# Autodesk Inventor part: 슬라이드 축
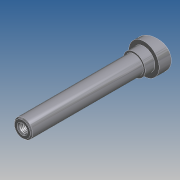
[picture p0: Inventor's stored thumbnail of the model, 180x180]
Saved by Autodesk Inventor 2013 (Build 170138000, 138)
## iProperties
Company: 한국ATC센터
Created: 2012-05
Part Number: 슬라이드 축
Document SubType Name: 모델링
Designer: KYOUNG IL JANG
Mass: 169.556 g
Surface Area: 67.5858 cm^2
Volume: 21.572 cm^3
Density: 7.86 g/cm^3
Material: 강, 연강
변환 표준: STEP AP214IS
파일 이름: C:\Users\SeoGD\Desktop\?쒗뿕\異?stp
전처리기: Build: 253, Release: 2010 SP1 - Date: Wed 07/29/2009
전송 단위: 밀리미터
불확실성: 0.01
Author: KYOUNG IL JANG
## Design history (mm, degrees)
sketch "스케치1"
  geometry: L1 (0, 100)-(7.5, 100); L2 (7.5, 100)-(7.5, 0); L3 (7.5, 0)-(12.5, 0); L4 (12.5, 0)-(12.5, -17); L5 (12.5, -17)-(0, -17); L6 (0, -17)-(0, 100); 1 further point
  constraints: 12 end point, 2 parallel, 2 point on line, 1 perpendicular, 1 vertical
  dimensions: "d0" = 100 distance from line of L1 point (0, 0); "d1" = 15 diameter of L2 L6; "d2" = 25 diameter of L4 L6; "d3" = 17 distance of L3.end L4.end
revolve "회전1" sketch "스케치1" stored, may be unused: angle "d4" = 90 deg
sketch "스케치2"
  geometry: L1 (12.5, 0)-(12.5, -17) reference; L2 (-12.5, -17)-(12.5, -17) reference; L3 (-12.5, 0)-(-12.5, -17) reference; L4 (12.5, -5)-(-12.5, -11.699); L5 (-12.5, 0)-(12.5, 0) reference; 1 further point
  constraints: 2 end point, 2 point on line
  dimensions: "d5" = 75 deg angle of L1 L4; "d6" = 5 distance from line of L4.start L5
extrude "돌출1" cut sketch "스케치2" stored distance "d7" = 10; taper "d8" = 0 deg
chamfer "모따기1" distance "d9" = 1; stored, may be unused: second distance "d10" = 2, angle "d11" = 45 deg
fillet "모깎기1" dims "d12" = 0.5
hole "구멍1" diameter "d15" = 6.647; stored, may be unused: countersink angle "d19" = 90 deg, drill point angle "d21" = 118 deg; dims "d13" = 10, "d14" = 10, "d16" = 17, "d17" = 4, "d18" = 2, "d20" = 20
chamfer "모따기2" distance "d22" = 1; stored, may be unused: second distance "d23" = 2, angle "d24" = 45 deg
sketch "스케치3"
  geometry: C1 r 9 at (0, 0); 1 further point
  constraints: 1 centre point, 1 coincident
  dimensions: "d25" = 18 diameter of C1
extrude "돌출2" join sketch "스케치3" distance "d26" = 8; taper "d27" = 0 deg
node "솔리드1"
node "솔리드 본체"
node "곡면 본체"
node "솔리드2"
